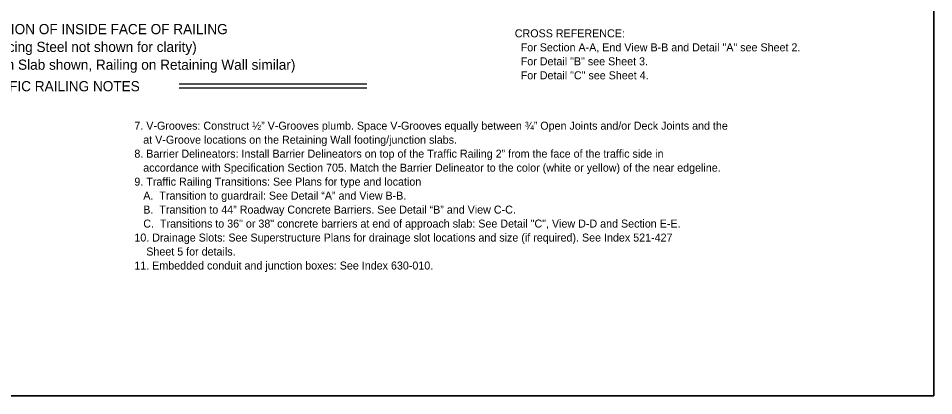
# Model space of a CAD drawing. Extents: x 0 to 41.1, y 0 to 25.9.
# Drawn here: x 18.01 to 41.05, y 0 to 9.5 of the extents above; entities that cross this region are included whole.
import ezdxf

# ---------------------------------------------------------------- set-up
doc = ezdxf.new("R2010")
doc.units = 0
for name, color, linetype in [('ActivePts-ConstElements', 7, 'Continuous'), ('Dimension', 7, 'Continuous'), ('Miscellaneous1', 7, 'Continuous'), ('TextStructures', 7, 'Continuous')]:
    doc.layers.add(name, color=color, linetype=linetype)

msp = doc.modelspace()

# ---------------------------------------------------------------- linework, layer by layer
at = {"layer": 'ActivePts-ConstElements'}
msp.add_lwpolyline([(0, 0), (41.051, 0), (41.051, 25.946), (0, 25.946)], close=True, dxfattribs=at)
at = {"layer": 'Dimension'}
for p, q in [((22.053, 7.849), (26.784, 7.849)), ((22.053, 7.746), (26.784, 7.746))]:
    msp.add_line(p, q, dxfattribs=at)
at = {"layer": 'Miscellaneous1'}
msp.add_lwpolyline([(0, 25.946), (41.051, 25.946), (41.051, 0), (0, 0)], close=True, dxfattribs=at)

# ---------------------------------------------------------------- texts
at = {"layer": 'Dimension'}
for s, height, p in [('ELEVATION OF INSIDE FACE OF RAILING', 0.256, (16.506, 9.101)), ('CROSS REFERENCE:', 0.2016, (30.505, 9.021)), ('(Reinforcing Steel not shown for clarity)', 0.256, (16.523, 8.653)), ('  For Section A-A, End View B-B and Detail "A" see Sheet 2.', 0.2016, (30.505, 8.669)), ('  For Detail "B" see Sheet 3.', 0.2016, (30.505, 8.317)), ('(Railing on Bridge Deck and Approach Slab shown, Railing on Retaining Wall similar)', 0.256, (12.081, 8.205)), ('  For Detail "C" see Sheet 4.', 0.2016, (30.505, 7.965))]:
    msp.add_text(s, height=height, dxfattribs=at).set_placement(p)
at = {"layer": 'TextStructures'}
for s, height, p in [('TRAFFIC RAILING NOTES', 0.256, (16.88, 7.664)), ('7. V-Grooves: Construct ½” V-Grooves plumb. Space V-Grooves equally between ¾” Open Joints and/or Deck Joints and the', 0.2016, (20.928, 6.696)), ('   at V-Groove locations on the Retaining Wall footing/junction slabs. ', 0.2016, (20.928, 6.344)), ('8. Barrier Delineators: Install Barrier Delineators on top of the Traffic Railing 2” from the face of the traffic side in', 0.2016, (20.928, 5.992)), ('   accordance with Specification Section 705. Match the Barrier Delineator to the color (white or yellow) of the near edgeline.', 0.2016, (20.928, 5.64)), ('9. Traffic Railing Transitions: See Plans for type and location', 0.2016, (20.928, 5.288)), ('   A.  Transition to guardrail: See Detail “A” and View B-B.', 0.2016, (20.928, 4.936)), ('   B.  Transition to 44” Roadway Concrete Barriers. See Detail “B” and View C-C.', 0.2016, (20.928, 4.584)), ('   C.  Transitions to 36" or 38" concrete barriers at end of approach slab: See Detail "C", View D-D and Section E-E.', 0.2016, (20.928, 4.232)), ('10. Drainage Slots: See Superstructure Plans for drainage slot locations and size (if required). See Index 521-427', 0.2016, (20.928, 3.88)), ('    Sheet 5 for details.', 0.2016, (20.928, 3.528)), ('11. Embedded conduit and junction boxes: See Index 630-010.', 0.2016, (20.928, 3.176))]:
    msp.add_text(s, height=height, dxfattribs=at).set_placement(p)

doc.saveas('drawing.dxf')
